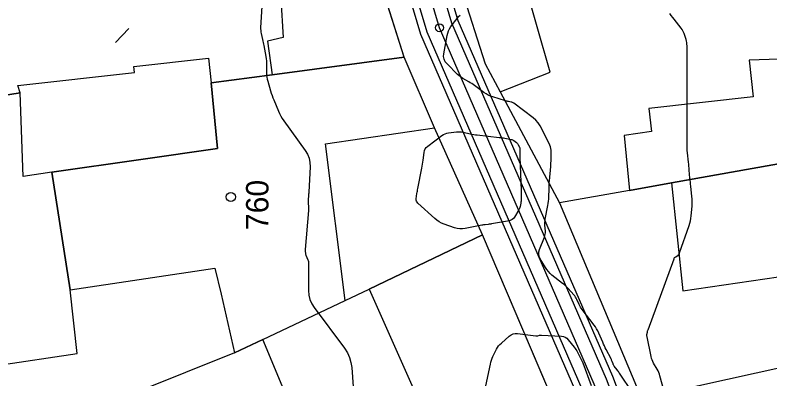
# Model space of a CAD drawing. Extents: x -534481 to -534262, y -1190577 to -1190138.
# Drawn here: x -534418.57 to -534390.01, y -1190477.55 to -1190463.81 of the extents above; entities that cross this region are included whole.
import ezdxf

# ---------------------------------------------------------------- set-up
doc = ezdxf.new("R2010")
doc.units = 0
for name, color, linetype in [('Bonity', 7, 'Continuous'), ('Definiční body', 7, 'Continuous'), ('Polygon budovy', 7, 'Continuous'), ('Polygon parcely', 7, 'Continuous'), ('Vrstva 18', 7, 'Continuous'), ('Vrstva 19', 7, 'Continuous'), ('Vrstva 35', 7, 'Continuous'), ('Vrstva 37', 7, 'Continuous'), ('Vrstva 46', 7, 'Continuous')]:
    doc.layers.add(name, color=color, linetype=linetype)

msp = doc.modelspace()

# ---------------------------------------------------------------- linework, layer by layer
at = {"layer": 'Bonity'}
msp.add_lwpolyline([(-534408.105, -1190518.46), (-534393.616, -1190502.389), (-534391.346, -1190496.962), (-534392.763, -1190488.017), (-534396.655, -1190477.752), (-534402.513, -1190464.283), (-534404.757, -1190456.741), (-534408.311, -1190433.088), (-534409.248, -1190427.879), (-534409.316, -1190416.054), (-534409.076, -1190409.418), (-534409.868, -1190391.439)], dxfattribs=at)
at = {"layer": 'Definiční body'}
for p, q in [((-534403.85, -1190465.4), (-534406.36, -1190457.46)), ((-534397.97, -1190470.9), (-534394.87, -1190478.28)), ((-534395.25, -1190485.32), (-534400.89, -1190472.11))]:
    msp.add_line(p, q, dxfattribs=at)
for points in [[(-534403.02, -1190457.53), (-534401.68, -1190462.84), (-534400.78, -1190465.65), (-534400.22, -1190466.7), (-534397.97, -1190470.9)], [(-534427.58, -1190468.08), (-534423.54, -1190467.58), (-534422.92, -1190467.48), (-534418.38, -1190466.74), (-534418.47, -1190466.47), (-534414.06, -1190465.97), (-534414.08, -1190465.75), (-534411.25, -1190465.44), (-534411.15, -1190466.36)], [(-534411.15, -1190466.36), (-534408.85, -1190466.06), (-534403.85, -1190465.4)], [(-534400.89, -1190472.11), (-534402.7, -1190468.07), (-534403.85, -1190465.4)], [(-534416.49, -1190474.19), (-534417.18, -1190469.74), (-534413.81, -1190469.26), (-534410.91, -1190468.85), (-534411.15, -1190466.36)], [(-534381.52, -1190467.98), (-534393.74, -1190470.15), (-534395.33, -1190470.44), (-534397.97, -1190470.9)], [(-534427.58, -1190468.08), (-534427.04, -1190471.5), (-534426.32, -1190476.24), (-534422.32, -1190477.5), (-534416.23, -1190476.59), (-534416.49, -1190474.19)], [(-534410.27, -1190476.57), (-534409.2, -1190476.06), (-534406.08, -1190474.59), (-534405.17, -1190474.16), (-534400.89, -1190472.11)], [(-534416.49, -1190474.19), (-534411.01, -1190473.37), (-534410.78, -1190474.35), (-534410.27, -1190476.57)], [(-534394.87, -1190478.28), (-534389.45, -1190477.08), (-534382.56, -1190476.12), (-534376.75, -1190475.31)], [(-534410.27, -1190476.57), (-534413.98, -1190478.05), (-534410.74, -1190485.76)]]:
    msp.add_lwpolyline(points, dxfattribs=at)
at = {"layer": 'Polygon parcely'}
for points in [[(-534399.31, -1190462.53), (-534388.45, -1190461.56), (-534388.15, -1190465.42), (-534390.79, -1190465.51), (-534390.65, -1190466.89), (-534394.59, -1190467.34), (-534394.49, -1190468.2), (-534395.52, -1190468.35), (-534395.33, -1190470.44), (-534393.74, -1190470.15), (-534381.52, -1190467.98), (-534382.5, -1190455.87), (-534388.94, -1190456.35), (-534391.43, -1190456.53), (-534398.69, -1190457.05), (-534403.02, -1190457.53), (-534401.68, -1190462.84), (-534400.78, -1190465.65), (-534400.22, -1190466.7), (-534398.32, -1190465.96)], [(-534428.92, -1190459.94), (-534427.58, -1190468.08), (-534423.54, -1190467.58), (-534422.92, -1190467.48), (-534423.48, -1190463.44), (-534417.22, -1190462.74), (-534408.6, -1190461.72), (-534408.43, -1190464.65), (-534409.02, -1190464.79), (-534408.85, -1190466.06), (-534403.85, -1190465.4), (-534406.36, -1190457.46), (-534408.34, -1190457.68), (-534409.38, -1190457.79), (-534412.88, -1190458.18), (-534418.64, -1190458.82), (-534418.67, -1190458.67), (-534423.88, -1190459.32)], [(-534406.83, -1190468.67), (-534402.7, -1190468.07), (-534403.85, -1190465.4), (-534408.85, -1190466.06), (-534411.15, -1190466.36), (-534410.91, -1190468.85), (-534413.81, -1190469.26), (-534417.18, -1190469.74), (-534416.49, -1190474.19), (-534411.01, -1190473.37), (-534410.78, -1190474.35), (-534410.27, -1190476.57), (-534409.2, -1190476.06), (-534406.08, -1190474.59)], [(-534423.54, -1190467.58), (-534422.32, -1190477.5), (-534416.23, -1190476.59), (-534416.49, -1190474.19), (-534417.18, -1190469.74), (-534418.27, -1190469.9), (-534418.38, -1190466.74), (-534422.92, -1190467.48)], [(-534393.74, -1190470.15), (-534393.31, -1190474.23), (-534382.96, -1190472.72), (-534382.56, -1190476.12), (-534376.75, -1190475.31), (-534377.78, -1190467.51), (-534381.52, -1190467.98)], [(-534413.98, -1190478.05), (-534410.74, -1190485.76), (-534408.96, -1190490.21), (-534408.72, -1190490.82), (-534395.25, -1190485.32), (-534400.89, -1190472.11), (-534405.17, -1190474.16), (-534402.3, -1190480.62), (-534406.62, -1190482.23), (-534409.2, -1190476.06), (-534410.27, -1190476.57)]]:
    msp.add_lwpolyline(points, close=True, dxfattribs=at)
at = {"layer": 'Vrstva 18'}
for points in [[(-534393.823, -1190478.7), (-534394.17, -1190477.437), (-534394.19, -1190477.373), (-534394.214, -1190477.311), (-534394.242, -1190477.25), (-534394.274, -1190477.191), (-534394.412, -1190476.96), (-534394.444, -1190476.901), (-534394.47, -1190476.84), (-534394.492, -1190476.778), (-534394.508, -1190476.713), (-534394.66, -1190475.962), (-534394.664, -1190475.94), (-534394.665, -1190475.918), (-534394.665, -1190475.896), (-534394.662, -1190475.874), (-534394.646, -1190475.785), (-534394.642, -1190475.762), (-534394.637, -1190475.741), (-534394.63, -1190475.719), (-534394.623, -1190475.698), (-534393.64, -1190473.017), (-534393.629, -1190472.993), (-534393.615, -1190472.971), (-534393.598, -1190472.952), (-534393.577, -1190472.936), (-534393.488, -1190472.875), (-534393.468, -1190472.858), (-534393.451, -1190472.839), (-534393.437, -1190472.818), (-534393.426, -1190472.794), (-534393.068, -1190471.755), (-534393.04, -1190471.667), (-534393.018, -1190471.578), (-534393.002, -1190471.488), (-534392.991, -1190471.396), (-534392.958, -1190471.025), (-534392.952, -1190470.935), (-534392.951, -1190470.845), (-534392.954, -1190470.755), (-534392.962, -1190470.665), (-534393.006, -1190470.277), (-534393.014, -1190470.201), (-534393.022, -1190470.125), (-534393.029, -1190470.048), (-534393.036, -1190469.972), (-534393.062, -1190469.666), (-534393.068, -1190469.59), (-534393.075, -1190469.513), (-534393.083, -1190469.437), (-534393.091, -1190469.361), (-534393.128, -1190469.012), (-534393.136, -1190468.928), (-534393.142, -1190468.844), (-534393.145, -1190468.76), (-534393.146, -1190468.676), (-534393.146, -1190464.963), (-534393.149, -1190464.904), (-534393.156, -1190464.846), (-534393.167, -1190464.789), (-534393.183, -1190464.732), (-534393.257, -1190464.507), (-534393.278, -1190464.452), (-534393.303, -1190464.4), (-534393.332, -1190464.35), (-534393.367, -1190464.302), (-534393.631, -1190463.964), (-534393.687, -1190463.892), (-534393.744, -1190463.821), (-534393.801, -1190463.75)], [(-534414.773, -1190464.845), (-534414.272, -1190464.316)], [(-534400.755, -1190477.821), (-534400.589, -1190476.994), (-534400.571, -1190476.92), (-534400.549, -1190476.848), (-534400.522, -1190476.777), (-534400.491, -1190476.709), (-534400.355, -1190476.437), (-534400.318, -1190476.371), (-534400.275, -1190476.31), (-534400.227, -1190476.253), (-534400.173, -1190476.2), (-534399.879, -1190475.941), (-534399.808, -1190475.89), (-534399.732, -1190475.856), (-534399.65, -1190475.841), (-534399.563, -1190475.843), (-534398.865, -1190475.927), (-534398.847, -1190475.928), (-534398.83, -1190475.928), (-534398.813, -1190475.926), (-534398.796, -1190475.922), (-534398.727, -1190475.904), (-534398.71, -1190475.9), (-534398.693, -1190475.898), (-534398.675, -1190475.896), (-534398.658, -1190475.897), (-534397.902, -1190475.941), (-534397.826, -1190475.953), (-534397.758, -1190475.979), (-534397.697, -1190476.02), (-534397.643, -1190476.074), (-534397.415, -1190476.358), (-534397.381, -1190476.402), (-534397.349, -1190476.448), (-534397.319, -1190476.496), (-534397.292, -1190476.545), (-534397.187, -1190476.745), (-534397.162, -1190476.795), (-534397.138, -1190476.846), (-534397.116, -1190476.898), (-534397.096, -1190476.95), (-534396.777, -1190477.804)]]:
    msp.add_lwpolyline(points, dxfattribs=at)
msp.add_lwpolyline([(-534401.64, -1190471.889), (-534401.741, -1190471.889), (-534401.842, -1190471.875), (-534401.941, -1190471.847), (-534402.338, -1190471.708), (-534402.435, -1190471.668), (-534402.526, -1190471.62), (-534402.611, -1190471.562), (-534402.692, -1190471.496), (-534403.332, -1190470.911), (-534403.363, -1190470.876), (-534403.383, -1190470.837), (-534403.393, -1190470.794), (-534403.392, -1190470.747), (-534403.366, -1190470.551), (-534403.359, -1190470.503), (-534403.351, -1190470.454), (-534403.342, -1190470.406), (-534403.333, -1190470.357), (-534403.178, -1190469.586), (-534403.164, -1190469.513), (-534403.151, -1190469.439), (-534403.14, -1190469.365), (-534403.131, -1190469.291), (-534403.097, -1190468.993), (-534403.082, -1190468.923), (-534403.054, -1190468.859), (-534403.013, -1190468.804), (-534402.959, -1190468.755), (-534402.426, -1190468.362), (-534402.367, -1190468.323), (-534402.304, -1190468.293), (-534402.238, -1190468.271), (-534402.169, -1190468.257), (-534401.876, -1190468.218), (-534401.81, -1190468.212), (-534401.744, -1190468.212), (-534401.678, -1190468.218), (-534401.612, -1190468.23), (-534401.35, -1190468.29), (-534401.284, -1190468.304), (-534401.218, -1190468.316), (-534401.152, -1190468.326), (-534401.085, -1190468.335), (-534400.251, -1190468.428), (-534400.199, -1190468.434), (-534400.148, -1190468.441), (-534400.098, -1190468.449), (-534400.047, -1190468.458), (-534399.801, -1190468.505), (-534399.773, -1190468.512), (-534399.746, -1190468.522), (-534399.721, -1190468.535), (-534399.697, -1190468.551), (-534399.598, -1190468.627), (-534399.579, -1190468.644), (-534399.562, -1190468.662), (-534399.547, -1190468.683), (-534399.535, -1190468.705), (-534399.49, -1190468.798), (-534399.48, -1190468.822), (-534399.473, -1190468.846), (-534399.469, -1190468.871), (-534399.468, -1190468.896), (-534399.472, -1190469.046), (-534399.473, -1190469.08), (-534399.473, -1190469.114), (-534399.472, -1190469.147), (-534399.471, -1190469.181), (-534399.421, -1190470.437), (-534399.419, -1190470.478), (-534399.419, -1190470.519), (-534399.419, -1190470.56), (-534399.419, -1190470.6), (-534399.423, -1190470.777), (-534399.424, -1190470.81), (-534399.427, -1190470.844), (-534399.432, -1190470.878), (-534399.438, -1190470.911), (-534399.464, -1190471.044), (-534399.471, -1190471.077), (-534399.482, -1190471.109), (-534399.495, -1190471.14), (-534399.512, -1190471.169), (-534399.676, -1190471.443), (-534399.714, -1190471.493), (-534399.758, -1190471.532), (-534399.811, -1190471.56), (-534399.87, -1190471.577), (-534400.544, -1190471.696), (-534400.575, -1190471.701), (-534400.605, -1190471.706), (-534400.636, -1190471.71), (-534400.667, -1190471.714), (-534400.79, -1190471.729), (-534400.821, -1190471.733), (-534400.851, -1190471.738), (-534400.882, -1190471.743), (-534400.912, -1190471.749), (-534401.537, -1190471.875)], close=True, dxfattribs=at)
at = {"layer": 'Vrstva 19'}
for points in [[(-534409.242, -1190463.48), (-534409.282, -1190464.272), (-534409.283, -1190464.33), (-534409.28, -1190464.388), (-534409.273, -1190464.446), (-534409.262, -1190464.503), (-534409.21, -1190464.731), (-534409.197, -1190464.788), (-534409.185, -1190464.845), (-534409.174, -1190464.902), (-534409.163, -1190464.959), (-534409.085, -1190465.377), (-534409.073, -1190465.454), (-534409.064, -1190465.531), (-534409.059, -1190465.609), (-534409.057, -1190465.688), (-534409.057, -1190466.001), (-534409.054, -1190466.079), (-534409.046, -1190466.157), (-534409.032, -1190466.233), (-534409.012, -1190466.309), (-534408.905, -1190466.673), (-534408.879, -1190466.758), (-534408.85, -1190466.843), (-534408.819, -1190466.927), (-534408.786, -1190467.01), (-534408.611, -1190467.435), (-534408.568, -1190467.531), (-534408.519, -1190467.625), (-534408.465, -1190467.716), (-534408.405, -1190467.803), (-534407.594, -1190468.918), (-534407.507, -1190469.061), (-534407.447, -1190469.212), (-534407.415, -1190469.371), (-534407.41, -1190469.539), (-534407.462, -1190470.498), (-534407.464, -1190470.533), (-534407.466, -1190470.567), (-534407.469, -1190470.602), (-534407.471, -1190470.637), (-534407.482, -1190470.775), (-534407.484, -1190470.81), (-534407.485, -1190470.844), (-534407.484, -1190470.879), (-534407.481, -1190470.914), (-534407.469, -1190471.055), (-534407.466, -1190471.09), (-534407.465, -1190471.125), (-534407.466, -1190471.161), (-534407.468, -1190471.196), (-534407.598, -1190472.667), (-534407.599, -1190472.685), (-534407.599, -1190472.702), (-534407.598, -1190472.72), (-534407.596, -1190472.738), (-534407.587, -1190472.809), (-534407.584, -1190472.827), (-534407.58, -1190472.844), (-534407.575, -1190472.861), (-534407.568, -1190472.878), (-534407.498, -1190473.05), (-534407.485, -1190473.084), (-534407.476, -1190473.12), (-534407.471, -1190473.156), (-534407.469, -1190473.192), (-534407.469, -1190474.208), (-534407.456, -1190474.385), (-534407.415, -1190474.553), (-534407.347, -1190474.712), (-534407.252, -1190474.862), (-534406.108, -1190476.396), (-534406, -1190476.564), (-534405.919, -1190476.742), (-534405.864, -1190476.93), (-534405.835, -1190477.127), (-534405.752, -1190478.22)], [(-534395.205, -1190478.07), (-534395.7, -1190477.339), (-534395.722, -1190477.307), (-534395.744, -1190477.275), (-534395.766, -1190477.244), (-534395.789, -1190477.214), (-534395.899, -1190477.069), (-534395.913, -1190477.049), (-534395.925, -1190477.028), (-534395.936, -1190477.006), (-534395.946, -1190476.983), (-534395.98, -1190476.891), (-534395.989, -1190476.868), (-534395.999, -1190476.845), (-534396.01, -1190476.823), (-534396.021, -1190476.801), (-534396.207, -1190476.444), (-534396.242, -1190476.377), (-534396.275, -1190476.309), (-534396.307, -1190476.241), (-534396.337, -1190476.172), (-534396.489, -1190475.823), (-534396.527, -1190475.744), (-534396.569, -1190475.666), (-534396.616, -1190475.592), (-534396.667, -1190475.52), (-534397.118, -1190474.929), (-534397.149, -1190474.886), (-534397.177, -1190474.841), (-534397.203, -1190474.795), (-534397.226, -1190474.748), (-534397.313, -1190474.554), (-534397.336, -1190474.507), (-534397.363, -1190474.462), (-534397.394, -1190474.42), (-534397.428, -1190474.379), (-534397.646, -1190474.141), (-534397.696, -1190474.089), (-534397.747, -1190474.04), (-534397.8, -1190473.992), (-534397.855, -1190473.947), (-534398.257, -1190473.629), (-534398.329, -1190473.567), (-534398.395, -1190473.498), (-534398.454, -1190473.424), (-534398.506, -1190473.344), (-534398.701, -1190473.011), (-534398.739, -1190472.927), (-534398.757, -1190472.841), (-534398.753, -1190472.754), (-534398.728, -1190472.665), (-534398.541, -1190472.194), (-534398.523, -1190472.141), (-534398.512, -1190472.087), (-534398.507, -1190472.031), (-534398.508, -1190471.975), (-534398.525, -1190471.749), (-534398.528, -1190471.692), (-534398.527, -1190471.636), (-534398.521, -1190471.58), (-534398.512, -1190471.524), (-534398.409, -1190470.997), (-534398.396, -1190470.921), (-534398.386, -1190470.844), (-534398.379, -1190470.766), (-534398.376, -1190470.689), (-534398.369, -1190470.377), (-534398.367, -1190470.3), (-534398.363, -1190470.222), (-534398.358, -1190470.144), (-534398.352, -1190470.067), (-534398.306, -1190469.533), (-534398.301, -1190469.464), (-534398.296, -1190469.395), (-534398.293, -1190469.327), (-534398.291, -1190469.258), (-534398.284, -1190468.982), (-534398.286, -1190468.914), (-534398.296, -1190468.848), (-534398.315, -1190468.783), (-534398.341, -1190468.72), (-534398.638, -1190468.106), (-534398.704, -1190467.987), (-534398.782, -1190467.879), (-534398.872, -1190467.781), (-534398.975, -1190467.692), (-534399.699, -1190467.135), (-534399.722, -1190467.12), (-534399.746, -1190467.108), (-534399.771, -1190467.098), (-534399.797, -1190467.092), (-534399.905, -1190467.071), (-534399.932, -1190467.066), (-534399.959, -1190467.059), (-534399.986, -1190467.053), (-534400.012, -1190467.045), (-534400.499, -1190466.899), (-534400.587, -1190466.868), (-534400.672, -1190466.83), (-534400.752, -1190466.785), (-534400.83, -1190466.732), (-534401.185, -1190466.468), (-534401.238, -1190466.43), (-534401.292, -1190466.394), (-534401.347, -1190466.36), (-534401.403, -1190466.328), (-534401.63, -1190466.202), (-534401.685, -1190466.168), (-534401.738, -1190466.131), (-534401.788, -1190466.091), (-534401.835, -1190466.047), (-534402.228, -1190465.653), (-534402.297, -1190465.569), (-534402.34, -1190465.476), (-534402.357, -1190465.375), (-534402.35, -1190465.267), (-534402.226, -1190464.581), (-534402.204, -1190464.49), (-534402.173, -1190464.404), (-534402.131, -1190464.321), (-534402.08, -1190464.243), (-534401.85, -1190463.932), (-534401.793, -1190463.865), (-534401.728, -1190463.806)]]:
    msp.add_lwpolyline(points, dxfattribs=at)
at = {"layer": 'Vrstva 35'}
for points in [[(-534405.407, -1190514.348), (-534394.258, -1190501.982), (-534392.12, -1190496.869), (-534393.492, -1190488.211), (-534397.35, -1190478.035), (-534403.219, -1190464.54), (-534405.491, -1190456.905), (-534409.051, -1190433.21), (-534409.998, -1190427.948), (-534410.066, -1190416.042), (-534409.827, -1190409.421), (-534410.645, -1190390.84)], [(-534405.057, -1190514.333), (-534394.044, -1190502.118), (-534391.862, -1190496.9), (-534393.249, -1190488.146), (-534397.118, -1190477.94), (-534402.983, -1190464.455), (-534405.247, -1190456.85), (-534408.804, -1190433.17), (-534409.748, -1190427.925), (-534409.816, -1190416.046), (-534409.577, -1190409.42), (-534410.397, -1190390.795)], [(-534403.656, -1190514.273), (-534393.187, -1190502.661), (-534390.83, -1190497.024), (-534392.278, -1190487.888), (-534396.191, -1190477.563), (-534402.042, -1190464.111), (-534404.268, -1190456.632), (-534407.818, -1190433.007), (-534408.749, -1190427.833), (-534408.816, -1190416.061), (-534408.576, -1190409.416), (-534409.363, -1190391.537)], [(-534403.306, -1190514.257), (-534392.973, -1190502.796), (-534390.572, -1190497.055), (-534392.035, -1190487.824), (-534395.96, -1190477.469), (-534401.807, -1190464.025), (-534404.023, -1190456.578), (-534407.571, -1190432.966), (-534408.499, -1190427.81), (-534408.566, -1190416.065), (-534408.326, -1190409.415), (-534409.111, -1190391.586)]]:
    msp.add_lwpolyline(points, dxfattribs=at)
at = {"layer": 'Vrstva 37'}
msp.add_circle((-534402.513, -1190464.283), 0.15, dxfattribs=at)
msp.add_circle((-534402.513, -1190464.283), 0.15, dxfattribs=at)
msp.add_circle((-534402.513, -1190464.283), 0.15, dxfattribs=at)
msp.add_circle((-534402.513, -1190464.283), 0.15, dxfattribs=at)
msp.add_circle((-534402.513, -1190464.283), 0.15, dxfattribs=at)
msp.add_circle((-534402.513, -1190464.283), 0.15, dxfattribs=at)
at = {"layer": 'Vrstva 46'}
msp.add_circle((-534410.411, -1190470.679), 0.175, dxfattribs=at)

# ---------------------------------------------------------------- texts
at = {"layer": 'Polygon budovy'}
msp.add_text('760', height=0.85, rotation=90, dxfattribs=at).set_placement((-534408.985, -1190471.93))

doc.saveas('drawing.dxf')
